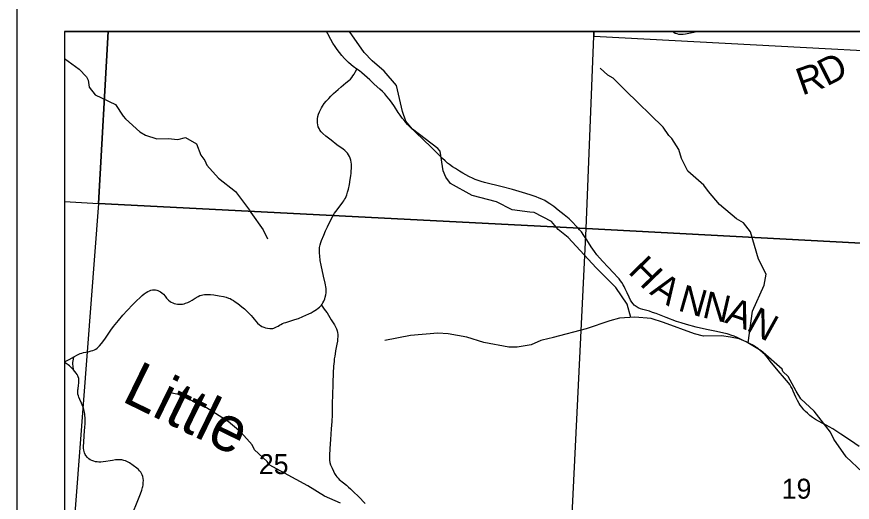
# Model space of a CAD drawing. Extents: x 0 to 34, y 0 to 22.
# Drawn here: x 2 to 3.753, y 19.912 to 20.931 of the extents above; entities that cross this region are included whole.
import ezdxf

# ---------------------------------------------------------------- set-up
doc = ezdxf.new("R2010")
doc.units = 0
for name, color, linetype in [('Default', 7, 'Continuous'), ('GM_X_County_Road', 7, 'Continuous'), ('GM_X_County_Road_Text', 7, 'Continuous'), ('GM_X_Minor_River', 7, 'Continuous'), ('GM_X_Minor_River_Text', 7, 'Continuous'), ('GM_X_Section', 7, 'Continuous'), ('GM_X_Section_Text', 7, 'Continuous'), ('GM_X_Township_Road', 7, 'Continuous'), ('GM_X_Township_Road_Text', 7, 'Continuous'), ('SH_Cut_Line', 7, 'Continuous'), ('SH_Data', 7, 'Continuous')]:
    doc.layers.add(name, color=color, linetype=linetype)

msp = doc.modelspace()

# ---------------------------------------------------------------- linework, layer by layer
at = {"layer": 'Default'}
for points in [[(2.1921, 20.9), (2.1, 20.9), (2.1, 20.5433), (2.1714, 20.5391)], [(3.2106, 20.9), (2.1921, 20.9), (2.1714, 20.5391), (3.1945, 20.4863), (3.2102, 20.8904)], [(4.2645, 20.9), (3.2106, 20.9), (3.2102, 20.8904), (4.26, 20.834)], [(2.1, 19.605), (2.1, 19.53), (3.1447, 19.4715), (3.1945, 20.4863), (2.1714, 20.5391)]]:
    msp.add_lwpolyline(points, close=True, dxfattribs=at)
msp.add_lwpolyline([(6.3694, 20.9), (2.1, 20.9), (2.1, 19.5179), (3.7007, 19.4348), (4.4284, 19.3984), (4.7013, 19.3856), (5.4875, 19.3459)], dxfattribs=at)
at = {"layer": 'GM_X_County_Road'}
msp.add_lwpolyline([(3.7671, 20.0288), (3.7488, 20.0417), (3.7286, 20.0548), (3.7114, 20.0659), (3.704, 20.0702), (3.6975, 20.0737), (3.6909, 20.0773), (3.682, 20.0818), (3.6755, 20.0856), (3.6693, 20.0899), (3.6637, 20.0941), (3.6583, 20.0987), (3.6544, 20.1024), (3.6512, 20.1057), (3.6467, 20.1112), (3.6435, 20.1157), (3.6413, 20.1189), (3.6375, 20.1254), (3.6343, 20.1321), (3.6314, 20.139), (3.6288, 20.1453), (3.6261, 20.1509), (3.6239, 20.1547), (3.6214, 20.1587), (3.6187, 20.1625), (3.6148, 20.1674), (3.6104, 20.1725), (3.5972, 20.1879), (3.5804, 20.208), (3.5744, 20.2154), (3.5698, 20.221), (3.5644, 20.2264), (3.5586, 20.2314), (3.5543, 20.2351), (3.5494, 20.2381), (3.5426, 20.242), (3.534, 20.2463), (3.5223, 20.2523), (3.5125, 20.257), (3.5047, 20.2603), (3.4978, 20.2629), (3.4942, 20.264), (3.4903, 20.2651), (3.4829, 20.2669), (3.4676, 20.27), (3.4468, 20.2743), (3.4251, 20.2797), (3.4047, 20.2851), (3.3938, 20.2884), (3.3836, 20.2916), (3.3621, 20.2996), (3.3412, 20.3079), (3.3338, 20.3105), (3.3269, 20.3127), (3.3129, 20.3166), (3.3081, 20.3182), (3.3035, 20.3201), (3.3012, 20.3213), (3.2991, 20.3225), (3.2972, 20.3239), (3.2953, 20.3256), (3.2928, 20.3282), (3.2903, 20.3316), (3.2877, 20.3359), (3.2845, 20.3426), (3.2806, 20.3511), (3.2765, 20.3599), (3.2742, 20.3645), (3.2719, 20.3684), (3.2691, 20.3728), (3.2665, 20.3765), (3.2634, 20.3806), (3.2603, 20.3844), (3.2525, 20.3928), (3.2398, 20.4059), (3.2294, 20.4171), (3.2222, 20.4249), (3.217, 20.4311), (3.2117, 20.438), (3.2046, 20.4483), (3.1956, 20.4625), (3.1893, 20.4721), (3.1844, 20.4792), (3.1807, 20.4839), (3.177, 20.4881), (3.1729, 20.4924), (3.1662, 20.4991), (3.1584, 20.5065), (3.1482, 20.5153), (3.1359, 20.5252), (3.1264, 20.5325), (3.118, 20.5382), (3.1124, 20.5418), (3.1074, 20.5449), (3.1013, 20.5479), (3.0959, 20.5503), (3.0896, 20.553), (3.0835, 20.5552), (3.0769, 20.5574), (3.0611, 20.5622), (3.0399, 20.5682), (3.0184, 20.5736), (2.9809, 20.5831), (2.9742, 20.5849), (2.97, 20.5862), (2.9661, 20.5876), (2.9619, 20.5893), (2.9576, 20.5911), (2.9486, 20.5954), (2.942, 20.5989), (2.936, 20.6023), (2.9285, 20.6068), (2.9201, 20.6122), (2.9139, 20.6162), (2.9077, 20.6205), (2.9033, 20.6239), (2.8984, 20.6282), (2.8929, 20.6337), (2.8848, 20.642), (2.8687, 20.6576), (2.8534, 20.6723), (2.837, 20.688), (2.8254, 20.6992), (2.8199, 20.705), (2.814, 20.7117), (2.8088, 20.7179), (2.804, 20.7241), (2.7998, 20.7302), (2.7921, 20.7425), (2.786, 20.7517), (2.7815, 20.7578), (2.7766, 20.7638), (2.7719, 20.7689), (2.7669, 20.774), (2.7615, 20.779), (2.7498, 20.7896), (2.7403, 20.7982), (2.7295, 20.8084), (2.7242, 20.8131), (2.7187, 20.8172), (2.7133, 20.8208), (2.7057, 20.8262), (2.7013, 20.8298), (2.6958, 20.8349), (2.6875, 20.8433), (2.6817, 20.8498), (2.6769, 20.8556), (2.672, 20.8621), (2.6678, 20.8683), (2.6633, 20.8758), (2.6591, 20.8832), (2.6526, 20.8953), (2.65, 20.9)], dxfattribs=at)
at = {"layer": 'GM_X_Minor_River'}
for points in [[(3.2879, 20.2994), (3.2805, 20.3277), (3.2566, 20.3626), (3.2155, 20.4038), (3.1569, 20.4676), (3.1355, 20.4846), (3.122, 20.501), (3.0852, 20.52), (3.0765, 20.5207), (3.0393, 20.526), (3.0061, 20.5423), (2.9555, 20.556), (2.9101, 20.5807), (2.9003, 20.5939), (2.8947, 20.6077), (2.8884, 20.6486), (2.8832, 20.6544), (2.83, 20.6952), (2.8162, 20.712), (2.8092, 20.732), (2.7965, 20.7867), (2.771, 20.8168), (2.7452, 20.8381), (2.7287, 20.8557), (2.6982, 20.9)], [(2.1, 20.843), (2.1313, 20.8207), (2.1463, 20.805), (2.1502, 20.7981), (2.152, 20.7828), (2.1648, 20.7668), (2.2069, 20.7465), (2.2235, 20.7224), (2.2279, 20.717), (2.2581, 20.6894), (2.2703, 20.6822), (2.2936, 20.675), (2.3178, 20.6757), (2.3377, 20.6736), (2.3541, 20.6772), (2.3768, 20.664), (2.3863, 20.6405), (2.3946, 20.6292), (2.3988, 20.6196), (2.423, 20.5919), (2.4592, 20.5641), (2.4882, 20.5248), (2.4907, 20.5198), (2.5168, 20.484), (2.526, 20.4651)], [(3.5343, 20.2468), (3.5435, 20.313), (3.5674, 20.3673), (3.5719, 20.3907), (3.5555, 20.422), (3.5391, 20.4798), (3.5245, 20.4981), (3.5097, 20.507), (3.4743, 20.5366), (3.4513, 20.5639), (3.4415, 20.5771), (3.4076, 20.6067), (3.3944, 20.6337), (3.3889, 20.6525), (3.3741, 20.6757), (3.3679, 20.6816), (3.356, 20.6995), (3.277, 20.7761), (3.2513, 20.8019), (3.2398, 20.8084), (3.224, 20.8229)], [(3.7737, 19.9752), (3.74, 20.0075), (3.7139, 20.0446), (3.707, 20.0591), (3.6726, 20.1031), (3.6446, 20.1292), (3.6351, 20.1448), (3.6177, 20.1759), (3.6067, 20.1866), (3.6056, 20.1915), (3.5659, 20.2264), (3.5613, 20.2298), (3.5299, 20.2487), (3.5152, 20.2551), (3.4974, 20.2585), (3.4785, 20.2615), (3.4403, 20.2607), (3.4214, 20.2655), (3.3564, 20.289), (3.331, 20.2973), (3.2963, 20.3006), (3.2645, 20.2986), (3.2437, 20.2929), (3.1946, 20.276), (3.1254, 20.2579)], [(3.1256, 20.2579), (3.102, 20.2522), (3.0994, 20.2515), (3.0793, 20.2423), (3.0499, 20.2377), (3.0325, 20.2372), (2.9799, 20.2474), (2.944, 20.2587), (2.9047, 20.2654), (2.8831, 20.2669), (2.8261, 20.2622), (2.7724, 20.2514)], [(2.6794, 19.9102), (2.6453, 19.9249), (2.6105, 19.9462), (2.5292, 19.9901), (2.525, 19.9976), (2.4986, 20.0219), (2.4936, 20.0325), (2.4709, 20.0583), (2.4656, 20.0625), (2.4437, 20.0815), (2.3979, 20.1102), (2.3419, 20.1371), (2.3227, 20.1412), (2.3227, 20.1409)]]:
    msp.add_lwpolyline(points, dxfattribs=at)
at = {"layer": 'GM_X_Section'}
for points in [[(3.2102, 20.8904), (4.26, 20.834), (4.2327, 20.4311), (4.2301, 20.4313), (3.1945, 20.4863)], [(3.1945, 20.4863), (4.2301, 20.4313), (4.1716, 19.4188), (3.1447, 19.4715)]]:
    msp.add_lwpolyline(points, close=True, dxfattribs=at)
at = {"layer": 'GM_X_Township_Road'}
for points in [[(3.3757, 20.9), (3.3782, 20.8984), (3.3813, 20.8967), (3.3846, 20.8955), (3.3877, 20.8947), (3.3912, 20.8943), (3.3944, 20.8943), (3.3979, 20.8946), (3.4029, 20.8952), (3.4095, 20.8963), (3.42, 20.8984), (3.4266, 20.9), (3.4268, 20.9)], [(2.1, 20.2067), (2.1003, 20.2068), (2.1027, 20.2077), (2.106, 20.2092), (2.1099, 20.2113), (2.1164, 20.2151), (2.12, 20.2172), (2.1273, 20.2214), (2.1304, 20.2229), (2.1334, 20.2242), (2.1368, 20.2251), (2.1401, 20.226), (2.15, 20.2279), (2.1561, 20.2294), (2.16, 20.2306), (2.1632, 20.2319), (2.166, 20.2333), (2.1687, 20.2351), (2.171, 20.2371), (2.1739, 20.2402), (2.1776, 20.2449), (2.1847, 20.2544), (2.1974, 20.2728), (2.2032, 20.2808), (2.2132, 20.2934), (2.2224, 20.3043), (2.2316, 20.3144), (2.2436, 20.327), (2.2506, 20.3339), (2.2595, 20.3426), (2.2631, 20.3459), (2.2674, 20.3494), (2.2714, 20.3522), (2.2752, 20.3542), (2.2784, 20.3558), (2.2814, 20.3568), (2.2846, 20.3575), (2.2877, 20.3576), (2.2908, 20.3575), (2.2936, 20.357), (2.2963, 20.3563), (2.299, 20.3552), (2.3017, 20.3537), (2.3046, 20.3515), (2.3076, 20.3485), (2.3111, 20.3442), (2.3144, 20.3402), (2.3182, 20.3363), (2.3216, 20.3336), (2.3243, 20.3319), (2.3277, 20.3303), (2.33, 20.3294), (2.3337, 20.3284), (2.3374, 20.3278), (2.341, 20.3274), (2.3443, 20.3275), (2.348, 20.328), (2.3511, 20.3287), (2.354, 20.3296), (2.3586, 20.3314), (2.3631, 20.3335), (2.3679, 20.3363), (2.3742, 20.3401), (2.3809, 20.344), (2.3843, 20.3455), (2.3877, 20.3467), (2.3907, 20.3475), (2.3937, 20.3479), (2.3968, 20.3481), (2.4008, 20.3481), (2.4063, 20.3478), (2.4132, 20.347), (2.4243, 20.3453), (2.4334, 20.3435), (2.4394, 20.3422), (2.4445, 20.3405), (2.4476, 20.3392), (2.4507, 20.3377), (2.4544, 20.3356), (2.4585, 20.3329), (2.4635, 20.3293), (2.4683, 20.3255), (2.4721, 20.3223), (2.4777, 20.3176), (2.4813, 20.3142), (2.4848, 20.3108), (2.4888, 20.307), (2.4917, 20.3038), (2.4954, 20.2997), (2.498, 20.2963), (2.5016, 20.2919), (2.5053, 20.2878), (2.5092, 20.2845), (2.5114, 20.2829), (2.5143, 20.281), (2.5183, 20.2792), (2.5219, 20.278), (2.5262, 20.277), (2.5306, 20.2765), (2.5343, 20.2765), (2.537, 20.2768), (2.5395, 20.2774), (2.5421, 20.2784), (2.5449, 20.2798), (2.5481, 20.2818), (2.551, 20.2835), (2.5543, 20.2853), (2.5576, 20.2869), (2.5612, 20.2883), (2.5647, 20.2895), (2.5685, 20.2907), (2.5749, 20.2926), (2.5831, 20.2953), (2.5907, 20.2979), (2.6, 20.3016), (2.6064, 20.3044), (2.6127, 20.3073), (2.6174, 20.3098), (2.6217, 20.3121), (2.6255, 20.3145), (2.6289, 20.3168), (2.6323, 20.3191), (2.6354, 20.3216), (2.6375, 20.3238), (2.6393, 20.3259), (2.6406, 20.3279), (2.6421, 20.3304), (2.6442, 20.3342), (2.646, 20.3389), (2.6471, 20.3425), (2.6483, 20.3474), (2.6489, 20.3517), (2.6491, 20.3542), (2.6491, 20.3567), (2.6491, 20.3603), (2.6486, 20.3642), (2.648, 20.3681), (2.6471, 20.372), (2.6437, 20.3862), (2.6386, 20.4094), (2.6368, 20.4195), (2.6356, 20.4288), (2.6352, 20.4347), (2.635, 20.4407), (2.6351, 20.4437), (2.6354, 20.4467), (2.6365, 20.4523), (2.6377, 20.4568), (2.6392, 20.461), (2.6439, 20.4724), (2.6477, 20.4816), (2.6516, 20.4903), (2.6574, 20.5021), (2.663, 20.5123), (2.6668, 20.5186), (2.6694, 20.5223), (2.6721, 20.5259), (2.6841, 20.5415), (2.686, 20.5443), (2.6878, 20.5473), (2.6893, 20.5503), (2.6908, 20.5534), (2.6921, 20.5568), (2.6931, 20.5597), (2.6941, 20.5627), (2.6956, 20.5687), (2.6978, 20.5791), (2.6994, 20.5891), (2.7007, 20.5967), (2.7015, 20.6023), (2.7018, 20.6073), (2.7021, 20.6121), (2.7021, 20.6172), (2.702, 20.6213), (2.7015, 20.6258), (2.7007, 20.6299), (2.6994, 20.6339), (2.6979, 20.6375), (2.6961, 20.6408), (2.6936, 20.6444), (2.6907, 20.6477), (2.6881, 20.6504), (2.685, 20.6529), (2.6715, 20.6624), (2.6596, 20.6717), (2.6487, 20.6802), (2.6422, 20.6856), (2.6387, 20.6892), (2.636, 20.6926), (2.6341, 20.6963), (2.6325, 20.7001), (2.6315, 20.7043), (2.6309, 20.7085), (2.6308, 20.7125), (2.6311, 20.7166), (2.6319, 20.7213), (2.6333, 20.7263), (2.6349, 20.7311), (2.637, 20.7356), (2.6392, 20.7397), (2.6415, 20.7434), (2.6452, 20.7486), (2.6492, 20.7536), (2.6545, 20.7596), (2.6588, 20.764), (2.6647, 20.7695), (2.6741, 20.7783), (2.6805, 20.7838), (2.6854, 20.7881), (2.6906, 20.7922), (2.6967, 20.797), (2.6999, 20.7999), (2.7028, 20.8032), (2.7053, 20.8068), (2.7076, 20.8107), (2.7099, 20.8148), (2.7133, 20.8208)], [(2.6393, 20.3259), (2.6436, 20.3196), (2.6472, 20.3144), (2.6508, 20.3092), (2.6598, 20.2949), (2.6663, 20.2845), (2.6686, 20.2802), (2.6706, 20.2758), (2.6719, 20.2717), (2.6728, 20.2679), (2.6732, 20.2638), (2.6733, 20.2593), (2.673, 20.2546), (2.6725, 20.2498), (2.6716, 20.2438), (2.6703, 20.2365), (2.6689, 20.2294), (2.6677, 20.2236), (2.6669, 20.2182), (2.6661, 20.2131), (2.6655, 20.2072), (2.6647, 20.1973), (2.664, 20.1825), (2.6633, 20.1625), (2.6624, 20.1348), (2.6618, 20.122), (2.6616, 20.11), (2.6614, 20.0951), (2.6606, 20.0815), (2.6596, 20.0659), (2.6581, 20.0435), (2.6569, 20.025), (2.656, 20.0097), (2.6558, 20.0048), (2.6561, 20), (2.6569, 19.9952), (2.6584, 19.9906), (2.6613, 19.9834), (2.6641, 19.9772), (2.6667, 19.9725), (2.6693, 19.9683), (2.6717, 19.9649), (2.674, 19.9623), (2.6766, 19.9596), (2.6852, 19.9527), (2.6915, 19.9477), (2.6962, 19.9437), (2.7004, 19.94), (2.7066, 19.934), (2.7166, 19.9238), (2.731, 19.9095)], [(2.1191, 20.1897), (2.1182, 20.1974), (2.1179, 20.2014), (2.1178, 20.205), (2.1182, 20.2086), (2.1189, 20.2122), (2.12, 20.2172)], [(2.2423, 19.8862), (2.2543, 19.9157), (2.2598, 19.9296), (2.2625, 19.9373), (2.2633, 19.9401), (2.264, 19.9428), (2.2645, 19.9452), (2.2649, 19.9477), (2.2653, 19.9506), (2.2655, 19.9533), (2.2656, 19.9577), (2.2651, 19.962), (2.2643, 19.9657), (2.2631, 19.9693), (2.2618, 19.9721), (2.2602, 19.9748), (2.2578, 19.9778), (2.2552, 19.9805), (2.2518, 19.9833), (2.2442, 19.9891), (2.2364, 19.9946), (2.2325, 19.9969), (2.2285, 19.9987), (2.2249, 19.9998), (2.2206, 20.0007), (2.2179, 20.0011), (2.2156, 20.0012), (2.2124, 20.0012), (2.2074, 20.0008), (2.2006, 19.9997), (2.1958, 19.9987), (2.1872, 19.9971), (2.1812, 19.9964), (2.1763, 19.9962), (2.1724, 19.9961), (2.1688, 19.9965), (2.165, 19.997), (2.1616, 19.9978), (2.1579, 19.9992), (2.1543, 20.0009), (2.1514, 20.003), (2.1482, 20.0058), (2.145, 20.0098), (2.1434, 20.0124), (2.1422, 20.0153), (2.1413, 20.0182), (2.1408, 20.0211), (2.1404, 20.0256), (2.1403, 20.0297), (2.1407, 20.0372), (2.1418, 20.0521), (2.1431, 20.0703), (2.1434, 20.0755), (2.1436, 20.0805), (2.1436, 20.0853), (2.1435, 20.0896), (2.1432, 20.0934), (2.1428, 20.0971), (2.1422, 20.1008), (2.1417, 20.1038), (2.141, 20.1066), (2.1399, 20.11), (2.1389, 20.1129), (2.1359, 20.1198), (2.1324, 20.1274), (2.1302, 20.1323), (2.1293, 20.1354), (2.1284, 20.1387), (2.1281, 20.1415), (2.128, 20.1447), (2.1283, 20.1475), (2.1286, 20.1501), (2.1296, 20.1573), (2.13, 20.1618), (2.1302, 20.1654), (2.1303, 20.1685), (2.13, 20.1717), (2.1292, 20.1748), (2.1279, 20.1775), (2.1266, 20.18), (2.1249, 20.1825), (2.1191, 20.1897), (2.1106, 20.1982), (2.1081, 20.2004), (2.1061, 20.202), (2.1038, 20.2033), (2.1015, 20.2045), (2.1, 20.2053)]]:
    msp.add_lwpolyline(points, dxfattribs=at)
at = {"layer": 'SH_Cut_Line'}
msp.add_lwpolyline([(8.9, 14.1), (8.9, 20.9), (2.1, 20.9), (2.1, 14.1)], dxfattribs=at)
at = {"layer": 'SH_Data'}
for p, q in [((2, 21), (2, 14)), ((2.1, 20.9), (2.1, 14.1)), ((2.1, 20.9), (8.9, 20.9))]:
    msp.add_line(p, q, dxfattribs=at)

# ---------------------------------------------------------------- texts
at = {"layer": 'GM_X_County_Road_Text'}
for s, rotation, p in [('H', 314.1525, (3.2805, 20.3947)), ('A', 326.6004, (3.3257, 20.3503)), ('N', 344.1566, (3.3847, 20.3148)), ('N', 347.0117, (3.4358, 20.3004)), ('A', 340.8618, (3.4829, 20.2896)), ('N', 330.9905, (3.5278, 20.2743))]:
    msp.add_text(s, height=0.0568, rotation=rotation, dxfattribs=at).set_placement(p)
at = {"layer": 'GM_X_Minor_River_Text'}
msp.add_text('Little', height=0.0947, rotation=333.998, dxfattribs=at).set_placement((2.2175, 20.1252))
at = {"layer": 'GM_X_Section_Text'}
for s, p in [('25', (2.5078, 19.971)), ('19', (3.6045, 19.9194))]:
    msp.add_text(s, height=0.04186, rotation=0, dxfattribs=at).set_placement(p)
at = {"layer": 'GM_X_Township_Road_Text'}
for s, rotation, p in [('D', 27.0523, (3.6989, 20.784)), ('R', 19.3915, (3.6474, 20.7653))]:
    msp.add_text(s, height=0.0568, rotation=rotation, dxfattribs=at).set_placement(p)

doc.saveas('drawing.dxf')
